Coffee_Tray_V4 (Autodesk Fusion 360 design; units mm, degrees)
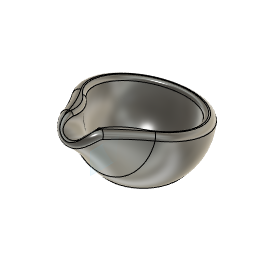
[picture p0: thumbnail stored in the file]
sphere_primitive "SpherePrimitive1" Diameter 100
sphere_primitive "SpherePrimitive2" Diameter 80
work_plane "WorkPlane1" AlongDistance -35
split "Split1"
work_plane "WorkPlane2" AlongDistance 50 (= "35.00 mm + 15 mm")
split "Split2"
remove_body "RemoveBody1"
remove_body "RemoveBody2"
sketch "Sketch3" plane through (0, 0, 15) normal (0, 0, 1) x axis (-1, 0, 0)
  line L1 (-20, -70.4128) -> (20, -70.4128)
  line L2 (-20, 70.4128) -> (-20, -70.4128)
  line L3 (20, 70.4128) -> (-20, 70.4128)
  line L4 (20, -70.4128) -> (20, 70.4128)
  line L5 (-20, 70.4128) -> (20, -70.4128)
  line L6 (20, 70.4128) -> (-20, -70.4128)
  circle C1 centre (0, 0) radius 37.081
  circle C2 centre (0, 0) radius 47.697
  point P7 (0, 0)
  point P2 (0, 0)
  point P5 (-20, 70.4128)
  point P6 (20, 70.4128)
  horizontal L1
  perpendicular L1 L2
  parallel L1 L3
  parallel L2 L4
  coincident L5 P7
  coincident L6 P7
  coincident P2 P7
  dimension "d5" distance P5 P6 = 40
extrude "Extrude1" add sketch "Sketch3" profile of C2 L2 L3 L4 against normal blind 20
sketch "Sketch5" plane through (20, 0, 0) normal (1, 0, 0) x axis (0, 1, 0)
  line L1 (-70.4128, 15) -> (-43.3013, 15)
  line L2 (-70.4128, -5) -> (-70.4128, 15)
  line L3 (-45.5522, -5) -> (-70.4128, -5)
  arc A1 centre (0, 0) radius 45.8258 clockwise from (-45.5522, -5) to (-43.3013, 15)
offset_faces "OffsetFaces2" distance 10
sketch "Sketch6" plane through (20, 0, 0) normal (1, 0, 0) x axis (0, 1, 0)
  line L1 (-70.4128, 25) -> (-38.4057, 25)
  line L2 (-70.4128, -5) -> (-70.4128, 25)
  line L3 (-45.5522, -5) -> (-70.4128, -5)
  line L4 (-45.5522, -5) -> (-49.7494, -5)
  line L5 (-38.4057, 25) -> (43.3013, 25)
  line L6 (-35.7071, -35) -> (35.7071, -35)
  line L7 (-58.7013, 27.403) -> (49.4771, -7.2124)
  line L8 (-32.4812, 49.3547) -> (-58.7013, 27.403)
  line L9 (58.1306, 45.4522) -> (-32.4812, 49.3547)
  line L10 (90.4484, 0.2073) -> (58.1306, 45.4522)
  line L11 (49.4771, -7.2124) -> (90.4484, 0.2073)
  line L12 (53.3332, -8.4463) -> (54.1964, -8.7225)
  line L13 (-62.5104, 28.6219) -> (53.3332, -8.4463)
  arc A1 centre (0, 0) radius 45.8258 clockwise from (-45.5522, -5) to (-38.4057, 25)
  arc A2 centre (0, 0) radius 45.8258 clockwise from (-45.5522, -5) to (-38.4057, 25)
  arc A3 centre (0, 0) radius 45.8258 clockwise from (-45.5522, -5) to (-38.4057, 25)
  circle C1 centre (0, 0) radius 50
  point P11 (43.3013, 25)
  point P15 (49.4771, -7.2124)
  concentric A1 C1
  coincident P11 C1
  coincident C1 P15
  parallel L7 L13
extrude "Extrude3" cut sketch "Sketch6" profile of A1 L1 A2 A3 L5 C1 L7 L8 L9 L10 L11 L13 distance 95
delete_face "DeleteFace1"
sketch "Sketch7" plane through (0, 2.5019, 7.8189) normal (0, 0.3048, 0.9524) x axis (-1, 0, 0)
  line L1 (-20, 45.0844) -> (-20, 76.5567)
  line L2 (20, 76.5567) -> (20, 45.0844)
  line L3 (-20, 76.5567) -> (20, 76.5567)
  line L4 (-10, -82.3736) -> (10, -82.3736)
  line L5 (-10, 82.3736) -> (-10, -82.3736)
  line L6 (10, 82.3736) -> (-10, 82.3736)
  line L7 (10, -82.3736) -> (10, 82.3736)
  line L8 (-10, 82.3736) -> (10, -82.3736)
  line L9 (10, 82.3736) -> (-10, -82.3736)
  arc A1 centre (0, 0) radius 49.3214 clockwise from (20, 45.0844) to (-20, 45.0844)
  circle C1 centre (0, 0) radius 39.1485
  point P11 (0, 0)
  point P5 (0, 0)
  point P9 (-10, 82.3736)
  point P10 (10, 82.3736)
  horizontal L4
  perpendicular L4 L5
  parallel L4 L6
  parallel L5 L7
  coincident L8 P11
  coincident L9 P11
  coincident P5 P11
  dimension "d23" distance P9 P10 = 20
extrude "Extrude4" cut sketch "Sketch7" profile of L3 C1 L5 L7 against normal blind 5
extrude "Extrude5" cut of existing geometry blind -9
fillet "Fillet5" radius 19.5
fillet "Fillet6" radius 10
sketch "Sketch8" plane through (0, -70.4128, 0) normal (0, -1, 0) x axis (1, 0, 0)
  line L1 (-20, 4.4369) -> (20, 4.4369)
  line L2 (-20, -5) -> (-20, 4.4369)
  line L3 (20, -5) -> (-20, -5)
  line L4 (20, 4.4369) -> (20, -5)
delete_face "DeleteFace2"
sketch "Sketch9" plane through (-20, 0, 0) normal (-1, 0, 0) x axis (0, -1, 0)
  line L1 (40.4377, 21.559) -> (70.4128, 31.1505)
  line L2 (70.4128, -5) -> (45.5522, -5)
  line L3 (70.4128, 31.1505) -> (70.4128, -5)
  line L4 (70.4128, 16.4513) -> (70.4128, 26.9507)
  line L5 (35.386, 15.7427) -> (70.4128, 26.9507)
  curve K1 (38.4116, 8.9213) -> (35.386, 15.7427)
  curve K2 (39.7384, 6.6372) -> (38.4116, 8.9213)
  curve K3 (35.386, 15.7427) -> (38.4116, 8.9213)
  line L6 (70.4128, 26.9507) -> (35.386, 15.7427)
  line L7 (70.4128, 26.9507) -> (35.386, 15.7427)
  line L8 (79.5587, -1.6316) -> (70.4128, 26.9507)
  line L9 (44.5319, -12.8397) -> (79.5587, -1.6316)
  line L10 (35.386, 15.7427) -> (44.5319, -12.8397)
  line L11 (63.7019, 47.9234) -> (79.5587, -1.6316)
  line L12 (28.6751, 36.7153) -> (63.7019, 47.9234)
  line L13 (44.5319, -12.8397) -> (28.6751, 36.7153)
  line L14 (79.5587, -1.6316) -> (44.5319, -12.8397)
  line L15 (70.4128, 26.9507) -> (35.386, 15.7427)
  line L16 (74.8209, 13.1749) -> (70.4128, 26.9507)
  line L17 (39.7941, 1.9668) -> (74.8209, 13.1749)
  line L18 (35.386, 15.7427) -> (39.7941, 1.9668)
  arc A1 centre (0, 0) radius 45.8258 clockwise from (40.4377, 21.559) to (45.5522, -5)
  point P7 (70.4128, 26.9507)
  point P13 (70.4128, 26.9507)
  point P9 (35.386, 15.7427)
  point P12 (35.386, 15.7427)
  point P20 (70.4128, 26.9507)
  point P19 (35.386, 15.7427)
  perpendicular L7 L8
  parallel L7 L9
  parallel L8 L10
  coincident P7 P13
  parallel L5 L7
  coincident P9 P12
  perpendicular L11 L12
  parallel L11 L13
  parallel L12 L14
  perpendicular L1 L11
  perpendicular L15 L16
  parallel L15 L17
  parallel L16 L18
  coincident P7 P20
  perpendicular L11 L15
  coincident P9 P19
extrude "Extrude6" add sketch "Sketch9" profile of L3 L4 L8 L9 L11 L14 L16 L17 against normal blind 40
extrude "Extrude7" cut sketch "Sketch9" profile of L1 L3 L11 against normal blind 57
delete_face "DeleteFace3"
delete_face "DeleteFace4"
delete_face "DeleteFace5"
sketch "Sketch10" plane through (0, -71.6957, 22.9415) normal (0, -0.9524, 0.3048) x axis (1, 0, 0)
  line L1 (-20, 8.2095) -> (-9.1652, 8.2095)
  line L2 (-20, -25.8005) -> (-20, 8.2095)
  line L3 (20, -25.8005) -> (-20, -25.8005)
  line L4 (20, 8.2095) -> (20, -25.8005)
  line L5 (10, 8.2095) -> (20, 8.2095)
  line L6 (10, 4.2095) -> (10, 8.2095)
  arc A1 centre (0, 4.2095) radius 10 clockwise from (10, 4.2095) to (-9.1652, 8.2095)
  circle C1 centre (0, 4.2095) radius 10
  circle C2 centre (0, 4.2095) radius 15
  concentric A1 C2
  dimension "d36" diameter C2 = 30
extrude "Extrude8" cut sketch "Sketch10" profile of L1 L2 L3 L4 L5 C2 against normal blind 29
remove_body "RemoveBody3"
delete_face "DeleteFace6"
delete_face "DeleteFace7"
fillet "Fillet7" radius 47.5
fillet "Fillet8" radius 163
delete_face "DeleteFace8"
delete_face "DeleteFace9"
delete_face "DeleteFace10"
offset_faces "OffsetFaces3" distance 5
work_plane "WorkPlane3" AlongDistance 115
work_plane "WorkPlane4" AlongDistance 135
sketch "Sketch11" plane through (135, 0, 0) normal (1, 0, 0) x axis (0, 1, 0)
  line L1 (-2.1642, 30.1442) -> (-11.7485, 30.1442)
  line L2 (-2.1642, 24.5792) -> (-2.1642, 30.1442)
  line L3 (-11.7485, 24.5792) -> (-2.1642, 24.5792)
  line L4 (-11.7485, 30.1442) -> (-11.7485, 24.5792)
  line L5 (-78.375, 30.1442) -> (50.0858, -3.5555)
  line L6 (-67.0903, 55.0326) -> (-78.375, 30.1442)
  line L7 (45.6028, 50.7042) -> (-67.0903, 55.0326)
  line L8 (50.0858, -3.5555) -> (45.6028, 50.7042)
  horizontal L1
  vertical L2
  horizontal L3
  vertical L4
extrude "Extrude9" cut sketch "Sketch11" against normal blind 265
sketch "Sketch12" plane through (0, 0, -35) normal (0, 0, -1) x axis (1, 0, 0)
  circle C1 centre (0, 0) radius 19.3649
  circle C2 centre (0, 0) radius 35.7071
extrude "Extrude10" add sketch "Sketch12" against normal blind 3
offset_faces "OffsetFaces4" distance 2
offset_faces "OffsetFaces5" distance -1
fillet "Fillet11" radius 16
delete_face "DeleteFace11"
fillet "Fillet12" radius 3
fillet "Fillet13" radius 5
